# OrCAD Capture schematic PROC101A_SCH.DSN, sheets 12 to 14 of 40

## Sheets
12 34.MCU GENERAL&SAFETY CONNECTOR: size C; title: MCU GENERAL & SAFETY CONNECTOR
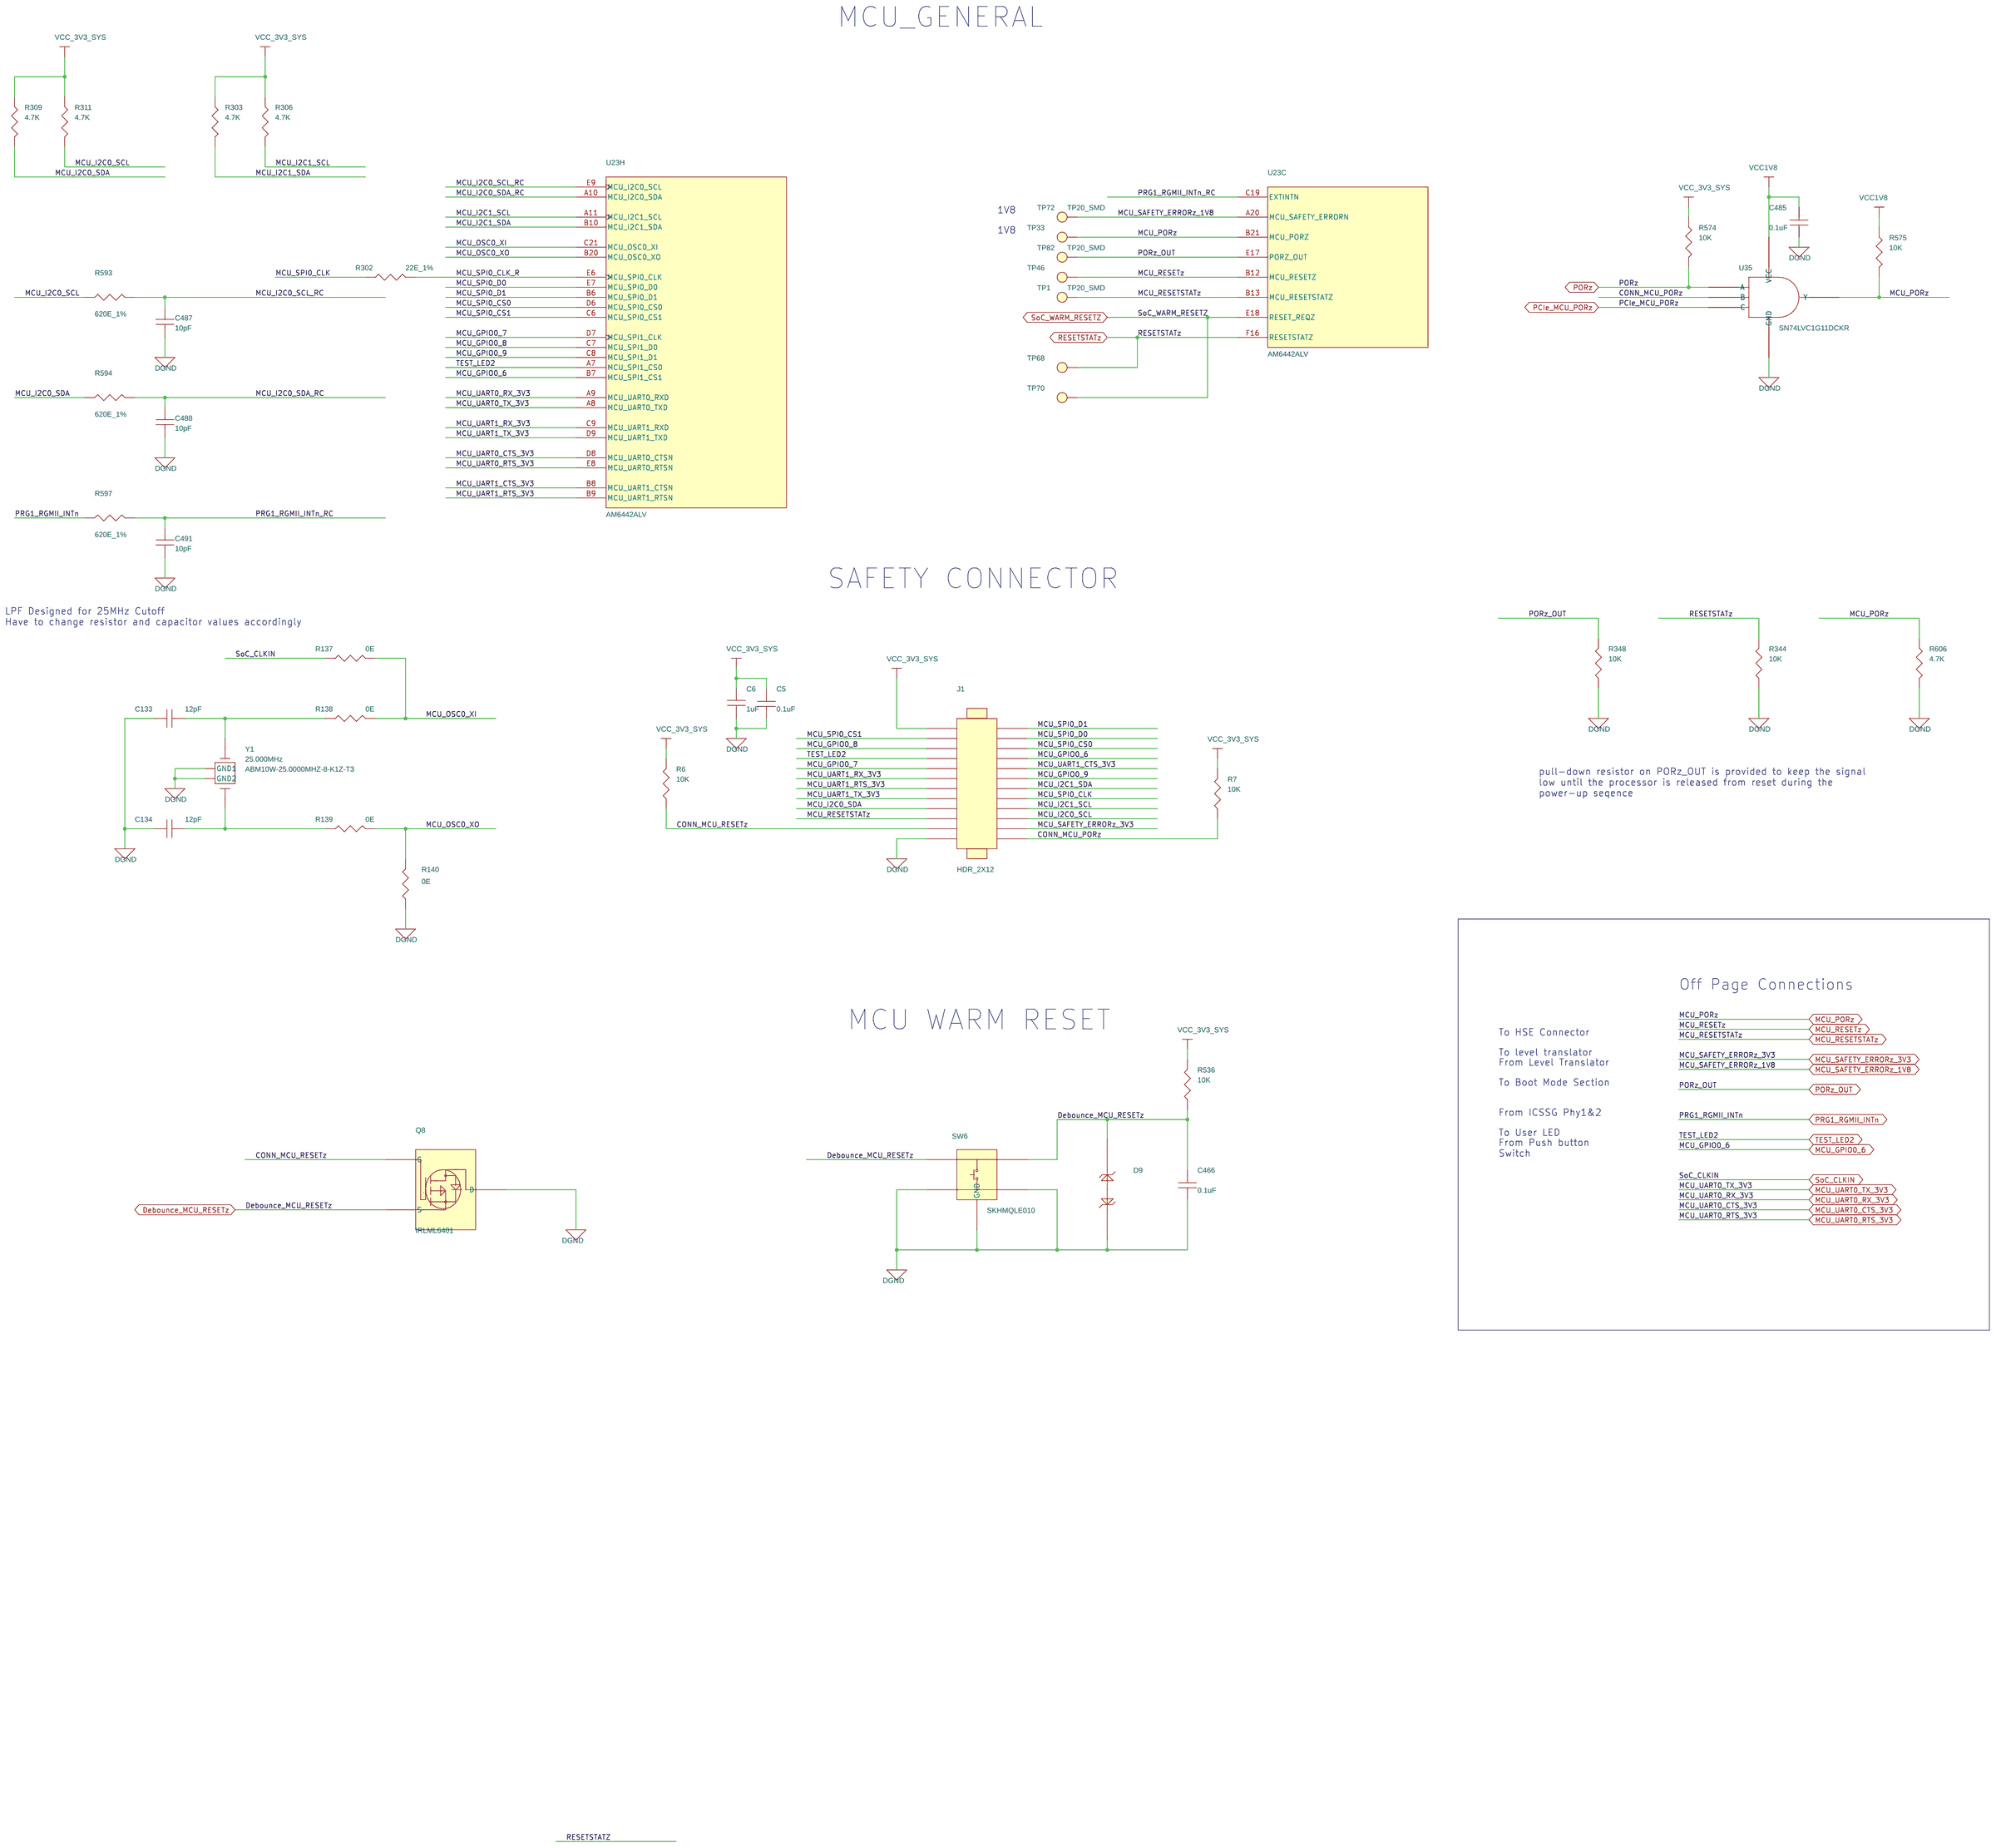
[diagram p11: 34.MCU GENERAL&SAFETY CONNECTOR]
13 33. IO EXPANDER & TEST HEADER: size C; title: IO EXPANDER
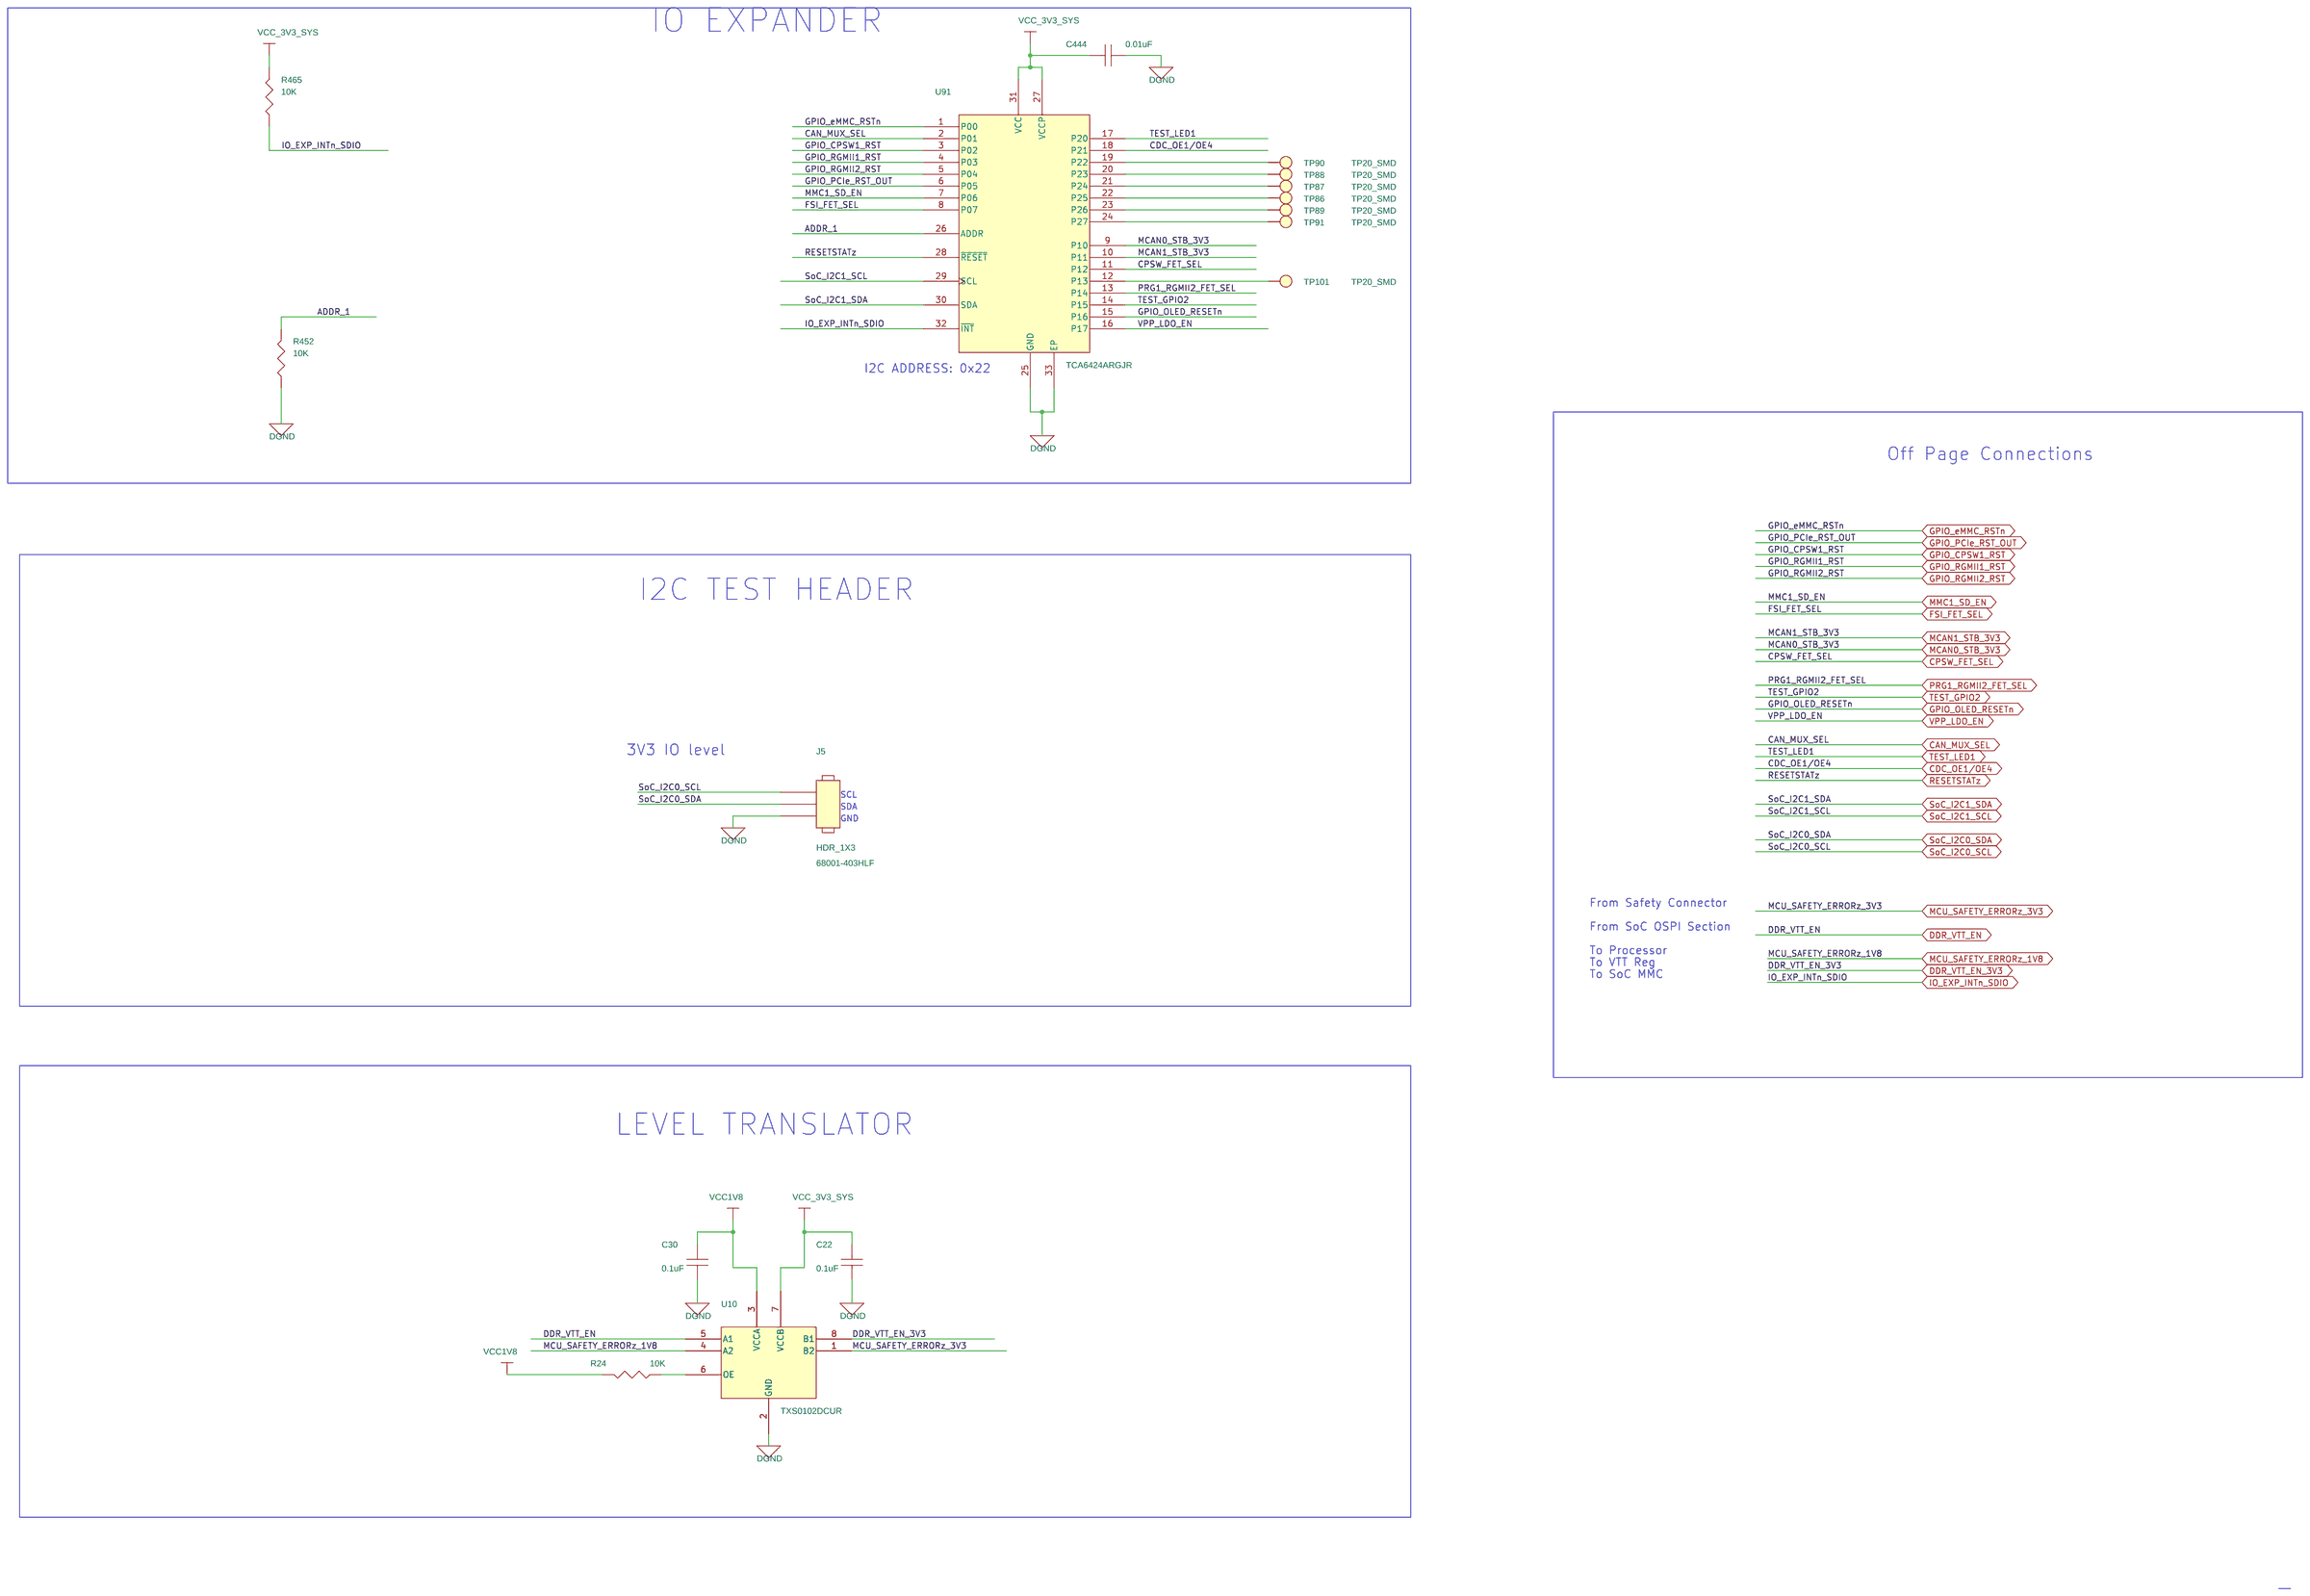
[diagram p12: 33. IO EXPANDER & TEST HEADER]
14 21. CURRENT MONITORING DEVICES: size C; title: CURRENT MONITORING DEVICES
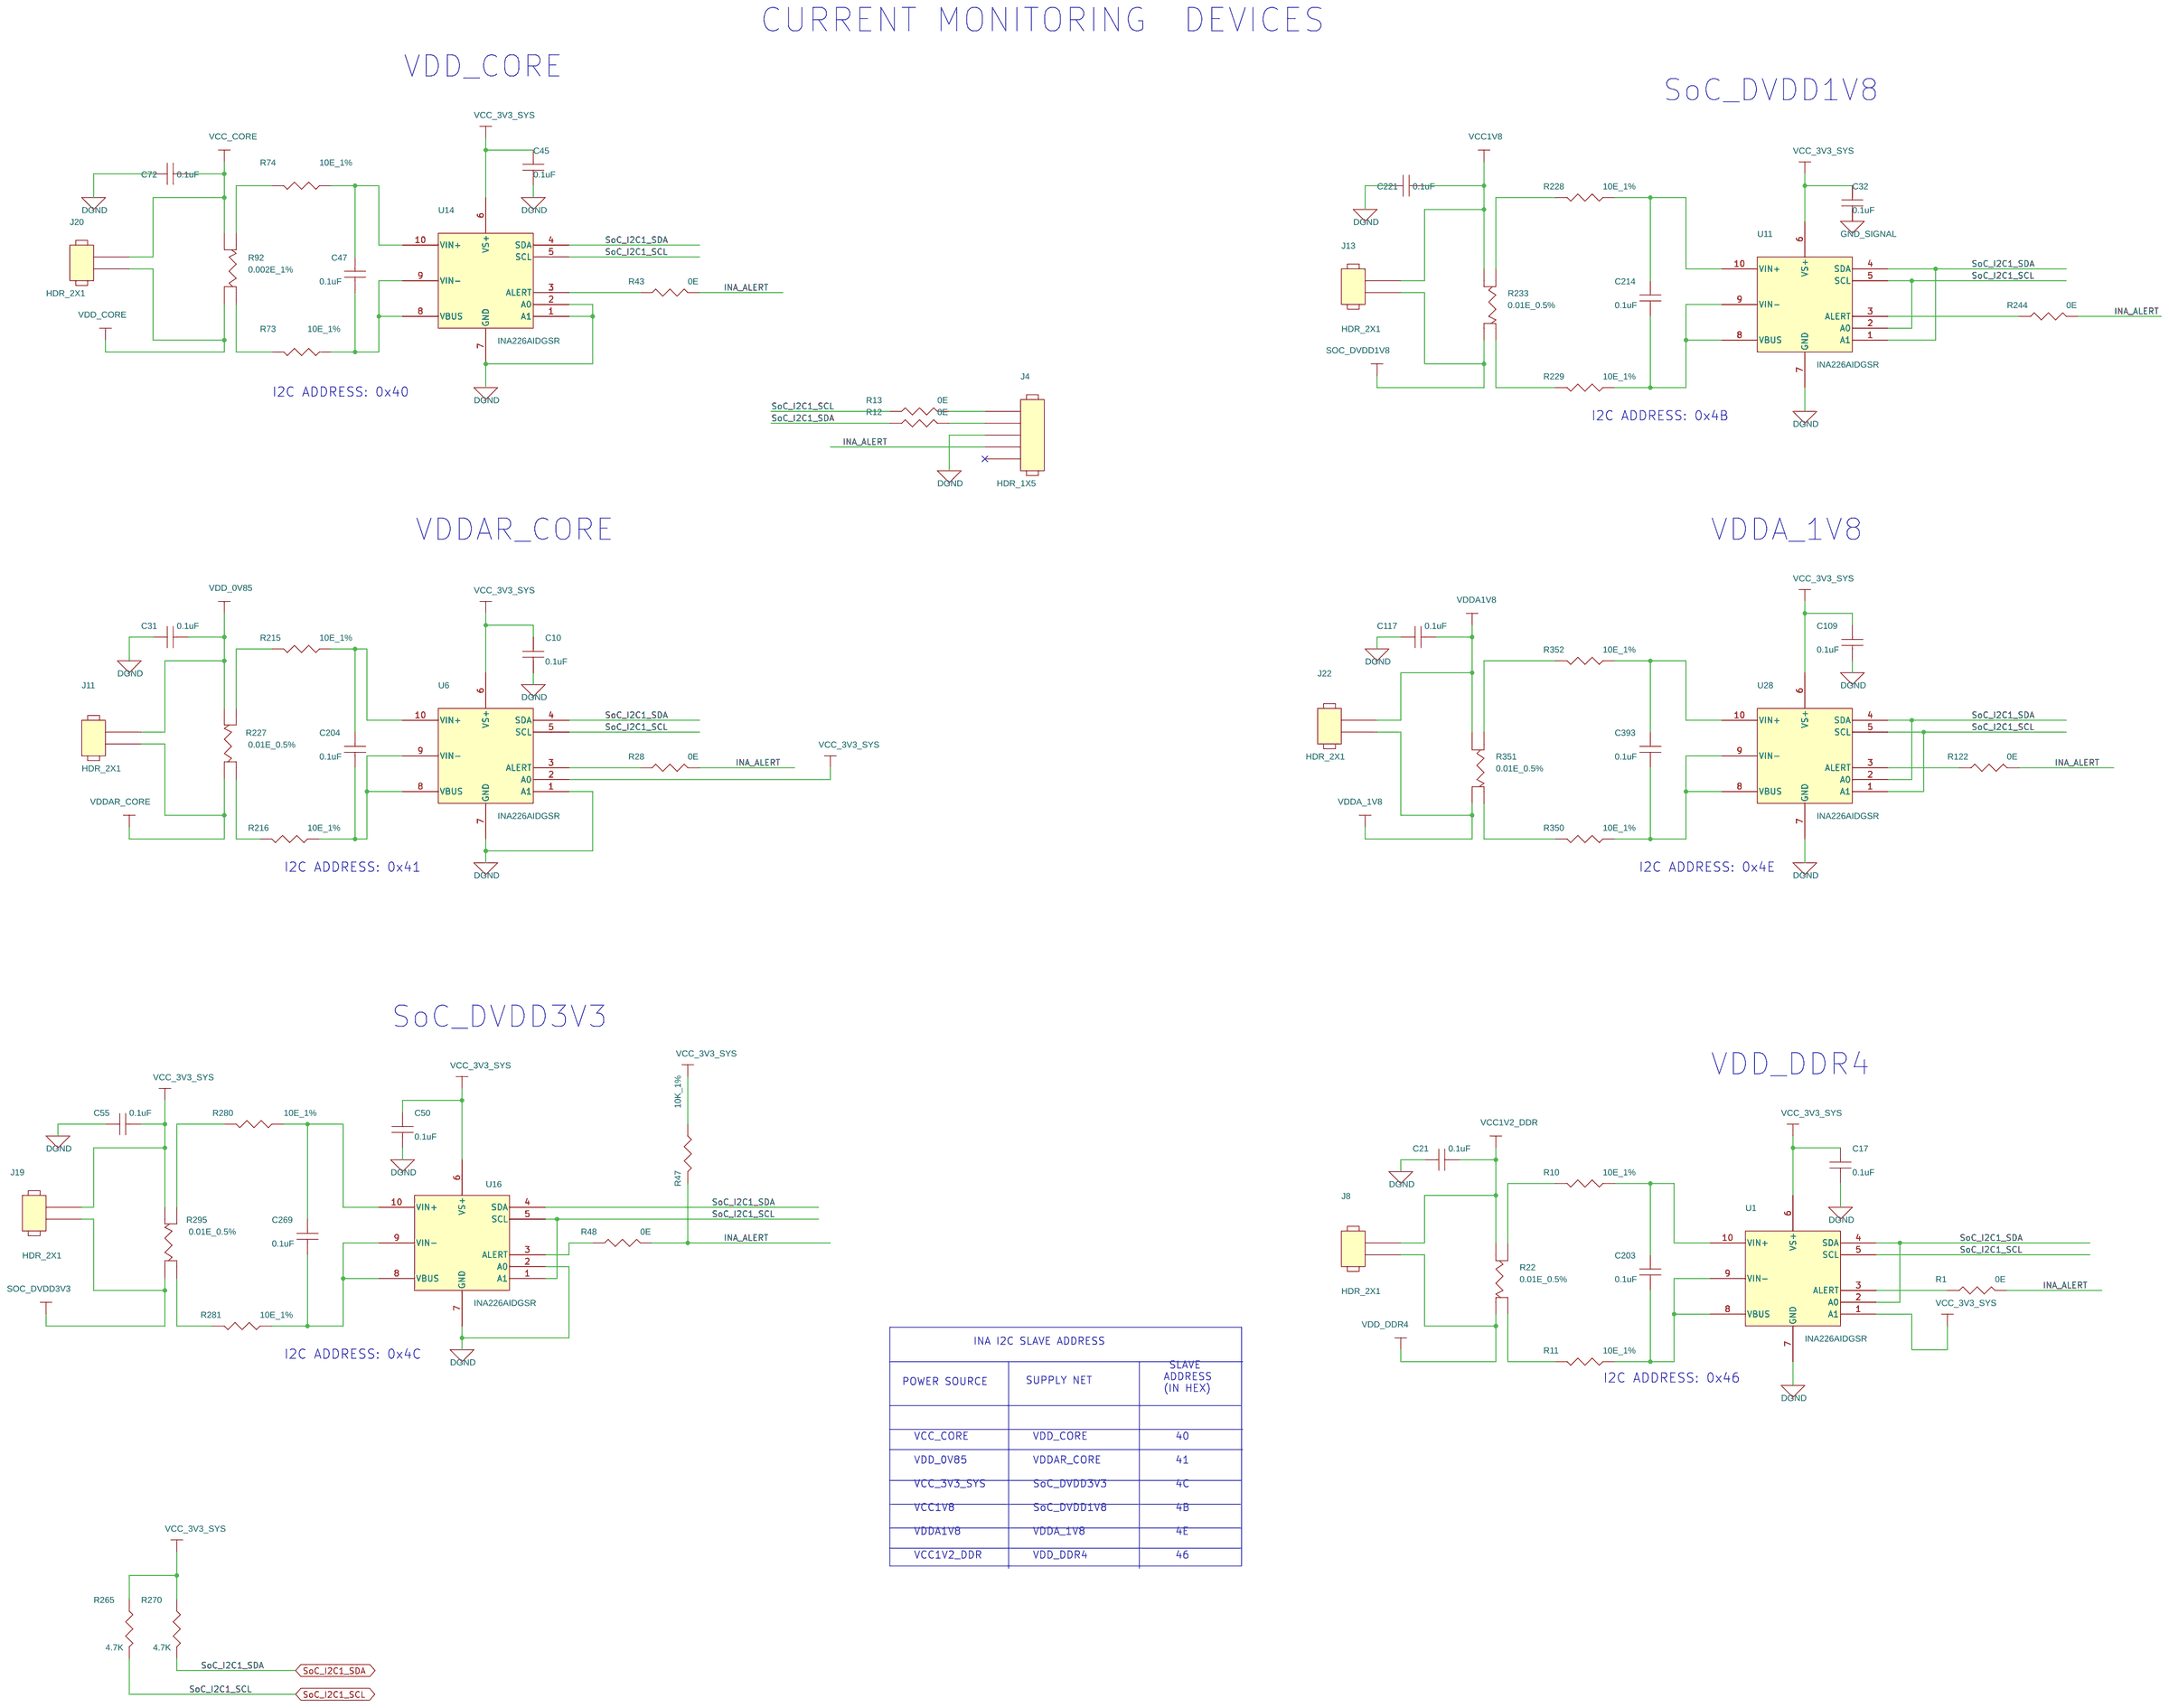
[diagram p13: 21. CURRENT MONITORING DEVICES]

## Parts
sheet 21. CURRENT MONITORING DEVICES
C10  0.1uF  [CAP0402_0-75]
C17  0.1uF  [CAP0402_0-75]
C21  0.1uF  [CAP0402_0-75]
C31  0.1uF  [CAP0402_0-75]
C32  0.1uF  [CAP0402_0-75]
C45  0.1uF  [CAP0402_0-75]
C47  0.1uF  [CAP0402_0-75]
C50  0.1uF  [CAP0402_0-75]
C55  0.1uF  [CAP0402_0-75]
C72  0.1uF  [CAP0402_0-75]
C109  0.1uF  [CAP0402_0-75]
C117  0.1uF  [CAP0402_0-75]
C203  0.1uF  [CAP0402_0-75]
C204  0.1uF  [CAP0402_0-75]
C214  0.1uF  [CAP0402_0-75]
C221  0.1uF  [CAP0402_0-75]
C269  0.1uF  [CAP0402_0-75]
C393  0.1uF  [CAP0402_0-75]
J4  HDR_1X5  [HDR_5X1_100_S_T_11-2]
J8  HDR_2X1  [HDR_2X1_100_S_T_10-8]
J11  HDR_2X1  [HDR_2X1_100_S_T_10-8]
J13  HDR_2X1  [HDR_2X1_100_S_T_10-8]
J19  HDR_2X1  [HDR_2X1_100_S_T_10-8]
J20  HDR_2X1  [HDR_2X1_100_S_T_10-8]
J22  HDR_2X1  [HDR_2X1_100_S_T_10-8]
R1  0E  [RES0402_0-5]
R10  10E_1%  [RES0402_0-5]
R11  10E_1%  [RES0402_0-5]
R12  0E  [RES0402_0-5]
R13  0E  [RES0402_0-5]
R22  0.01E_0.5%  [RES1206-4TERM_0-75]
R28  0E  [RES0402_0-5]
R43  0E  [RES0402_0-5]
R47  10K_1%  [RES0402_0-5]
R48  0E  [RES0402_0-5]
R73  10E_1%  [RES0402_0-5]
R74  10E_1%  [RES0402_0-5]
R92  0.002E_1%  [RES2512-4TERM_0-75]
R122  0E  [RES0402_0-5]
R215  10E_1%  [RES0402_0-5]
R216  10E_1%  [RES0402_0-5]
R227  0.01E_0.5%  [RES1206-4TERM_0-75]
R228  10E_1%  [RES0402_0-5]
R229  10E_1%  [RES0402_0-5]
R233  0.01E_0.5%  [RES1206-4TERM_0-75]
R244  0E  [RES0402_0-5]
R265  4.7K  [RES0402_0-5]
R270  4.7K  [RES0402_0-5]
R280  10E_1%  [RES0402_0-5]
R281  10E_1%  [RES0402_0-5]
R295  0.01E_0.5%  [RES1206-4TERM_0-75]
R350  10E_1%  [RES0402_0-5]
R351  0.01E_0.5%  [RES1206-4TERM_0-75]
R352  10E_1%  [RES0402_0-5]
U1  INA226AIDGSR  [MSOP10_19-68_120X120_1-1]
U6  INA226AIDGSR  [MSOP10_19-68_120X120_1-1]
U11  INA226AIDGSR  [MSOP10_19-68_120X120_1-1]
U14  INA226AIDGSR  [MSOP10_19-68_120X120_1-1]
U16  INA226AIDGSR  [MSOP10_19-68_120X120_1-1]
U28  INA226AIDGSR  [MSOP10_19-68_120X120_1-1]
sheet 28.GPMC & FSI CONNECTOR
U23  AM6442ALV  [FCBGA441_31-49_680X680_2-6]  (sections A,B,C,D,E,F,G,H,I,J,K,L,M,N,O,P)
sheet 33. IO EXPANDER & TEST HEADER
C22  0.1uF  [CAP0402_0-75]
C30  0.1uF  [CAP0402_0-75]
C444  0.01uF  [CAP0402_0-75]
J5  HDR_1X3  [HDR_3X1_100_S_T]
R24  10K  [RES0402_0-5]
R452  10K  [RES0402_0-5]
R465  10K  [RES0402_0-5]
TP86  TP20_SMD  [TP20_SMD]
TP87  TP20_SMD  [TP20_SMD]
TP88  TP20_SMD  [TP20_SMD]
TP89  TP20_SMD  [TP20_SMD]
TP90  TP20_SMD  [TP20_SMD]
TP91  TP20_SMD  [TP20_SMD]
TP101  TP20_SMD  [TP20_SMD]
U10  TXS0102DCUR  [VSSOP8_19-68_85X95_0-9]
U91  TCA6424ARGJR  [QFN32_19-68_200X200]
sheet 34.MCU GENERAL&SAFETY CONNECTOR
C5  0.1uF  [CAP0402_0-75]
C6  1uF  [CAP0402_0-75]
C133  12pF  [CAP0201_0-5]
C134  12pF  [CAP0201_0-5]
C466  0.1uF  [CAP0402_0-75]
C485  0.1uF  [CAP0402_0-75]
C487  10pF  [CAP0402_0-75]
C488  10pF  [CAP0402_0-75]
C491  10pF  [CAP0402_0-75]
D9  TPD1E10B06DPYR  [DIO_DFN0402_0-5]
J1  HDR_2X12  [HDR_2X12_TSW-112-07-D_S_T_8-6]
Q8  IRLML6401  [TO_SOT23-123]
R6  10K  [RES0402_0-5]
R7  10K  [RES0402_0-5]
R137  0E  [RES0402_0-5]
R138  0E  [RES0402_0-5]
R139  0E  [RES0402_0-5]
R140  0E  [RES0402_0-5]
R302  22E_1%  [RES0402_0-5]
R303  4.7K  [RES0402_0-5]
R306  4.7K  [RES0402_0-5]
R309  4.7K  [RES0402_0-5]
R311  4.7K  [RES0402_0-5]
R344  10K  [RES0402_0-5]
R348  10K  [RES0402_0-5]
R536  10K  [RES0402_0-5]
R574  10K  [RES0402_0-5]
R575  10K  [RES0402_0-5]
R593  620E_1%  [RES0402_0-5]
R594  620E_1%  [RES0402_0-5]
R597  620E_1%  [RES0402_0-5]
R606  4.7K  [RES0402_0-5]
SW6  SKHMQLE010  [SW4_SKHMQLE010_240X260_SMD_3-1]
TP1  TP20_SMD  [TP20_SMD]
TP33  TP20_SMD  [TP20_SMD]
TP46  TP20_SMD  [TP20_SMD]
TP68  TP20_SMD  [TP20_SMD]
TP70  TP20_SMD  [TP20_SMD]
TP72  TP20_SMD  [TP20_SMD]
TP82  TP20_SMD  [TP20_SMD]
U35  SN74LVC1G11DCKR  [SC70-6]
Y1  25.000MHz  [XTAL4_ABM10W_100X80_SMD_0-6]

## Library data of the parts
C5 C10 C17 C21 C22 C30-C32 C45 C47 C50 C55 C72 C109 C117 C203 C204 C214 C221 C269 C393 C466 C485 = CAP: CAP CERAMIC 0.1uF 25V 20% X5R 0402; Alt_Mfr_name: YAGEO AMERICA; Alt_Mfr_part_number: CC0402KRX5R8BB104; Chkd/date: MANIRAJA/170820; Crtd /date: ALVY/170820; Custom_Duty: 15%; Customs_HS_Code: 85322990; Distributor_name: DIGIKEY; Distributor_part_number: 732-7495-1-ND; Footprint Path: Y:\MIS_DATABASE\Library\ALTIUM_TOOL\PCB_FOOTPRINTS\Altium_Footprint_Lib.PcbLib; Height: 0.55MM; Library Path: Y:\MIS_DATABASE\Library\ALTIUM_TOOL\SCHEMATICS_PARTS\MS_DISCRETE_Library.schlib; Mfr_name: WURTH ELECTRONICS; Mfr_part_number: 885012105018; Mistral Part No: 120020080003-R; Package: 0402; Part_type: CAPACITORS\CERAMIC; Project: AM64x_EVM_BRD; RoHS: RoHS; Temperature: -55°C+85°C; Tolerance: 20%; Voltage: 25V; Wattage: NA; Weight: 0.65mg; Datasheet: Y:\MIS_DATABASE\DATASHEETS\CAPACITORS\885012105018.PDF
J4 = HEADER_5X1: CON HDR 1X5 2.54MM PITCH ST TH; Chkd/date: VASANTHA/310117; Crtd /date: MAZHAR/280405; Custom_Duty: 24%; Customs_HS_Code: 85369090; Distributor_name: DIGIKEY; Distributor_part_number: WM4003-ND; Footprint Path: Y:\MIS_DATABASE\Library\ALTIUM_TOOL\PCB_FOOTPRINTS\Altium_Footprint_Lib.PcbLib; Height: 11.17MM; Library Path: Y:\MIS_DATABASE\Library\ALTIUM_TOOL\SCHEMATICS_PARTS\MS_CONNECTOR_Library.schlib; Mfr_name: MOLEX; Mfr_part_number: 22-03-2051; Mistral Part No: 150009030262-R; Package: THRU-HOLE; Part_type: CONNECTOR\HEADERS; Project: HSWD; RoHS: RoHS; Temperature: NA; Tolerance: NA; Voltage: NA; Wattage: NA; Weight: 343mg; Datasheet: Y:\MIS_DATABASE\DATASHEETS\CONNECTORS\MOLEX022032021.PDF
J8 J11 J13 J19 J20 J22 = HEADER_2X1: CON HDR 2X1 2.54MM PITCH ST TH; Chkd/date: VASANTHA/060117; Crtd /date: MAZHAR/280405; Custom_Duty: 24%; Customs_HS_Code: 85369090; Distributor_name: DIGIKEY; Distributor_part_number: WM4000-ND; Footprint Path: Y:\MIS_DATABASE\Library\ALTIUM_TOOL\PCB_FOOTPRINTS\Altium_Footprint_Lib.PcbLib; Height: 10.79MM; Library Path: Y:\MIS_DATABASE\Library\ALTIUM_TOOL\SCHEMATICS_PARTS\MS_Connector_Library.schlib; Mfr_name: MOLEX; Mfr_part_number: 22-03-2021; Mistral Part No: 150009030246-R; Package: THRU-HOLE; Part_type: CONNECTOR\HEADERS; Project: FPGA EXTENDER CARD; RoHS: RoHS; Temperature: -0°C+75°C; Tolerance: NA; Voltage: NA; Wattage: NA; Weight: 139gm; Datasheet: Y:\MIS_DATABASE\DATASHEETS\CONNECTORS\HEADER_X4030.PDF
R1 R12 R13 R28 R43 R48 R122 R137-R140 R244 = RESISTOR: RES 0E 1/16W JUMPER 0402; Chkd/date: VASANTHA/201216; Crtd /date: MUDDU/190810; Custom_Duty: 15%; Customs_HS_Code: 85332119; Distributor_name: DIGIKEY; Distributor_part_number: 541-0.0JCT-ND; Footprint Path: Y:\MIS_DATABASE\Library\ALTIUM_TOOL\PCB_FOOTPRINTS\Altium_Footprint_Lib.PcbLib; Height: 0.40MM; Library Path: Y:\MIS_DATABASE\Library\ALTIUM_TOOL\SCHEMATICS_PARTS\MS_DISCRETE_Library.schlib; Mfr_name: VISHAY; Mfr_part_number: CRCW04020000Z0ED; Mistral Part No: 110010080019-R; Package: 0402; Part_type: RESISTORS\FIXED; Project: PB_BUGBASE; RoHS: RoHS; Temperature: -55°C+155°C; Tolerance: NA; Voltage: NA; Wattage: 1/16W; Weight: 0.65mg; Datasheet: Y:\MIS_DATABASE\DATASHEETS\RESISTORS\CRCW0603.PDF
R10 R11 R73 R74 R215 R216 R228 R229 R280 R281 R350 R352 = RESISTOR: RES 10E 1/16W 1% 0402; Chkd/date: MANIRAJA/070218; Crtd /date: ALVY/070218; Custom_Duty: 15%; Customs_HS_Code: 85332119; Distributor_name: DIGIKEY; Distributor_part_number: 311-10.0LRCT-ND; Footprint Path: Y:\MIS_DATABASE\Library\ALTIUM_TOOL\PCB_FOOTPRINTS\Altium_Footprint_Lib.PcbLib; Height: 0.40MM; Library Path: Y:\MIS_DATABASE\Library\ALTIUM_TOOL\SCHEMATICS_PARTS\MS_DISCRETE_Library.schlib; Mfr_name: YAGEO AMERICA; Mfr_part_number: RC0402FR-0710RL; Mistral Part No: 110018020004-R; Package: 0402; Part_type: RESISTORS\FIXED; Project: TI_MAXIE_CPB; RoHS: RoHS; Temperature: -55°C+155°C; Tolerance: 1%; Voltage: NA; Wattage: 1/16W; Weight: 0.65mg; Datasheet: Y:\MIS_DATABASE\DATASHEETS\RESISTORS\RCXXXXL-SER_MAR18.PDF
R22 R227 R233 R295 R351 = RESISTOR-4TERM: RES 0.01E 1/2W 0.5% 1206-4; Chkd/date: MANIRAJA/260917; Crtd /date: MANIRAJA/260917; Custom_Duty: 15%; Customs_HS_Code: 85332119; Distributor_name: DIGIKEY; Distributor_part_number: LVK12R010DERCT-ND; Footprint Path: Y:\MIS_DATABASE\Library\ALTIUM_TOOL\PCB_FOOTPRINTS\Altium_Footprint_Lib.PcbLib; Height: 0.65MM; Library Path: Y:\MIS_DATABASE\Library\ALTIUM_TOOL\SCHEMATICS_PARTS\MS_DISCRETE_Library.schlib; Mfr_name: OHMITE; Mfr_part_number: LVK12R010DER; Mistral Part No: 110017090009-R; Package: 1206-4; Part_type: RESISTORS\FIXED; Project: TI_MAXIE_CPB; RoHS: RoHS; Temperature: -40°C+125°C; Tolerance: 0.5%; Voltage: NA; Wattage: 1/2W; Weight: 16.2mg; Datasheet: Y:\MIS_DATABASE\DATASHEETS\RESISTORS\LVK-SERIES.PDF
R47 = RESISTOR: RES 10K 1/16W 1% 0402; Chkd/date: VASANTHA/201216; Crtd /date: GEETHA/290506; Custom_Duty: 15%; Customs_HS_Code: 85332119; Distributor_name: DIGIKEY; Distributor_part_number: 311-10.0KLRTR-ND; Footprint Path: Y:\MIS_DATABASE\Library\ALTIUM_TOOL\PCB_FOOTPRINTS\Altium_Footprint_Lib.PcbLib; Height: 0.40MM; Library Path: Y:\MIS_DATABASE\Library\ALTIUM_TOOL\SCHEMATICS_PARTS\MS_DISCRETE_Library.schlib; Mfr_name: YAGEO AMERICA; Mfr_part_number: RC0402FR-0710KL; Mistral Part No: 110015090015-R; Package: 0402; Part_type: RESISTORS\FIXED; Project: VOCERA; RoHS: RoHS; Temperature: -55°C+155°C; Tolerance: 1%; Voltage: NA; Wattage: 1/16W; Weight: 0.65mg; Datasheet: Y:\MIS_DATABASE\DATASHEETS\RESISTORS\RCXXXXL-SER_MAR18.PDF
R92 = RESISTOR-4TERM: RES 0.002E 2W 1% 2512-4; Chkd/date: MANIRAJA/260917; Crtd /date: MANIRAJA/260917; Custom_Duty: 15%; Customs_HS_Code: 85332119; Distributor_name: DIGIKEY; Distributor_part_number: LVK25R002FERCT-ND; Footprint Path: Y:\MIS_DATABASE\Library\ALTIUM_TOOL\PCB_FOOTPRINTS\Altium_Footprint_Lib.PcbLib; Height: 0.70MM; Library Path: Y:\MIS_DATABASE\Library\ALTIUM_TOOL\SCHEMATICS_PARTS\MS_DISCRETE_Library.schlib; Mfr_name: OHMITE; Mfr_part_number: LVK25R002FER; Mistral Part No: 110017090010-R; Package: 2512-4; Part_type: RESISTORS\FIXED; Project: TI_MAXIE_CPB; RoHS: RoHS; Temperature: -40°C+125°C; Tolerance: 1%; Voltage: NA; Wattage: 2W; Weight: NA; Datasheet: Y:\MIS_DATABASE\DATASHEETS\RESISTORS\LVK-SERIES.PDF
R265 R270 R303 R306 R309 R311 R606 = RESISTOR: RES 4.7K 1/16W 5% 0402; Chkd/date: VASANTHA/130516; Crtd /date: VASANTHA/130516; Custom_Duty: 15%; Customs_HS_Code: 85332119; Distributor_name: DIGIKEY; Distributor_part_number: 311-4.7KJRCT-ND; Footprint Path: Y:\MIS_DATABASE\Library\ALTIUM_TOOL\PCB_FOOTPRINTS\Altium_Footprint_Lib.PcbLib; Height: 0.40MM; Library Path: Y:\MIS_DATABASE\Library\ALTIUM_TOOL\SCHEMATICS_PARTS\MS_DISCRETE_Library.schlib; Mfr_name: YAGEO AMERICA; Mfr_part_number: RC0402JR-074K7L; Mistral Part No: 110011060001-R; Package: 0402; Part_type: RESISTORS\FIXED; Project: TMDXCSK368; RoHS: RoHS; Temperature: -55°C+155°C; Tolerance: 5%; Voltage: NA; Wattage: 1/16W; Weight: 0.65mg; Datasheet: Y:\MIS_DATABASE\DATASHEETS\RESISTORS\RCXXXXL-SER_MAR18.PDF
U1 U6 U11 U14 U16 U28 = INA226AIDGS_MSOP10: IC BI-DIRECTIONAL CURRENT MONITER MSOP10; Chkd/date: MANIRAJA/050417; Crtd /date: MANIRAJA/050417; Custom_Duty: 15%; Customs_HS_Code: 85423100; Distributor_name: DIGIKEY; Distributor_part_number: 296-29034-1-ND; Footprint Path: Y:\MIS_DATABASE\Library\ALTIUM_TOOL\PCB_FOOTPRINTS\Altium_Footprint_Lib.PcbLib; Height: 1.10MM; Library Path: Y:\MIS_DATABASE\Library\ALTIUM_TOOL\SCHEMATICS_PARTS\MS_MISCINTERFACE_Library.schlib; Mfr_name: TEXAS INSTRUMENTS; Mistral Part No: 141011080019-R; Package: MSOP10; Part_type: ICS\INTERFACE; Project: DM385EVM_BASE-BOARD; RoHS: RoHS; Temperature: -40°C+125°C; Tolerance: NA; Voltage: NA; Wattage: NA; Weight: NA; Datasheet: Y:\MIS_DATABASE\DATASHEETS\ICS\INTERFACE\INA226.PDF
U23 = AM64-SVB_BGA441: IC AM64 SoC MICROPROCESSOR BGA441; Chkd/date: MANIRAJA/020520; Crtd /date: ALVY/090420; Custom_Duty: 15%; Customs_HS_Code: 85423100; Distributor_name: NA; Distributor_part_number: NA; Footprint Path: Y:\MIS_DATABASE\Library\ALTIUM_TOOL\PCB_FOOTPRINTS\Altium_Footprint_Lib.PcbLib; Height: 2.57MM; Library Path: Y:\MIS_DATABASE\Library\ALTIUM_TOOL\SCHEMATICS_PARTS\MS_MICROPROCESSOR_Library.schlib; Mfr_name: TEXAS INSTRUMENTS; Mfr_part_number: AM6442ASFGGAALV; Mistral Part No: 141220040002; Package: BGA441; Part_type: ICS\DIGITAL\MICROPROCESSOR; Project: AM64x_SVB BRD; RoHS: NA; Temperature: NA; Tolerance: NA; Voltage: NA; Wattage: NA; Weight: NA; Datasheet: Y:\MIS_DATABASE\DATASHEETS\ICS\DIGITAL\MICROCONTROLLER\AM64-SoC_SVB.PDF
C444 = CAP: CAP CERAMIC 0.01uF 25V 10% X7R 0402; Chkd/date: MANIRAJA/170820; Crtd /date: ALVY/170820; Custom_Duty: 15%; Customs_HS_Code: 85322990; Distributor_name: DIGIKEY; Distributor_part_number: 732-7545-1-ND; Footprint Path: Y:\MIS_DATABASE\Library\ALTIUM_TOOL\PCB_FOOTPRINTS\Altium_Footprint_Lib.PcbLib; Height: 0.55MM; Library Path: Y:\MIS_DATABASE\Library\ALTIUM_TOOL\SCHEMATICS_PARTS\MS_DISCRETE_Library.schlib; Mfr_name: WURTH ELECTRONICS; Mfr_part_number: 885012205050; Mistral Part No: 120011090040-R; Package: 0402; Part_type: CAPACITORS\CERAMIC; Project: AM64x_EVM_BRD; RoHS: RoHS; Temperature: -55°C+125°C; Tolerance: 10%; Voltage: 25V; Wattage: NA; Weight: 0.65mg; Datasheet: Y:\MIS_DATABASE\DATASHEETS\CAPACITORS\885012205050.PDF
J5 = HEADER_3X1: HDR 1X3 2.54MM PITCH ST TH; Chkd/date: VASANTHA/290616; Crtd /date: VASANTHA/290616; Custom_Duty: 15%; Customs_HS_Code: 85322990; Distributor_name: DIGIKEY; Distributor_part_number: 609-3471-ND; Height: 8.58MM; Mfr_name: FCI; Mfr_part_number: 68001-403HLF; Mistral Part No: 150016060025-R; Package: THRU-HOLE; Part_type: CONNECTOR\HEADERS; Project: IKEYP; RoHS: RoHS; Temperature: -40°C+105°C; Tolerance: NA; Voltage: NA; Wattage: NA; Weight: NA; Datasheet: Y:\MIS_DATABASE\DATASHEETS\CONNECTORS\68000.PDF
R6 R7 R24 R344 R348 R452 R465 R536 R574 R575 = RESISTOR: RES 10K 1/16W 5% 0402; Chkd/date: VASANTHA/061216; Crtd /date: MAZHAR/230805; Custom_Duty: 15%; Customs_HS_Code: 85332119; Distributor_name: DIGIKEY; Distributor_part_number: 311-10KJRCT-ND; Footprint Path: Y:\MIS_DATABASE\Library\ALTIUM_TOOL\PCB_FOOTPRINTS\Altium_Footprint_Lib.PcbLib; Height: 0.40MM; Library Path: Y:\MIS_DATABASE\Library\ALTIUM_TOOL\SCHEMATICS_PARTS\MS_DISCRETE_Library.schlib; Mfr_name: YAGEO AMERICA; Mfr_part_number: RC0402JR-0710KL; Mistral Part No: 110011060021-R; Package: 0402; Part_type: RESISTORS\FIXED; Project: HSE; RoHS: RoHS; Temperature: -55°C+155°C; Tolerance: 5%; Voltage: NA; Wattage: 1/16W; Weight: 0.65mg; Datasheet: Y:\MIS_DATABASE\DATASHEETS\RESISTORS\RCXXXXL-SER_MAR18.PDF
TP1 TP33 TP46 TP68 TP70 TP72 TP82 TP86-TP91 TP101 = TESTPOINT: TESTPOINT CIR 20 SMD; Chkd/date: SHREESHAIL/171006; Crtd /date: MAZHAR/171006; Custom_Duty: NA; Customs_HS_Code: NA; Distributor_name: NA; Distributor_part_number: NA; Footprint Path: Y:\MIS_DATABASE\Library\ALTIUM_TOOL\PCB_FOOTPRINTS\Altium_Footprint_Lib.PcbLib; Height: NA; Library Path: Y:\MIS_DATABASE\Library\ALTIUM_TOOL\SCHEMATICS_PARTS\MS_DISCRETE_Library.schlib; MECHANICAL 3D STEP FILE: NA; Mfr_name: LOCAL; Mistral Part No: NA; Package: SMD; Project: BT MODULE_CSRBC04; RoHS: NA; Temperature: NA; Tolerance: NA; Voltage: NA; Wattage: NA; Weight: NA; Datasheet: NA
U10 = TXS0102DCUR_VSSOP8: IC 2BIT BI-DIR VOLTAGE-LEVEL TRANSLATOR US8(VSSOP8); Chkd/date: MANIRAJA/130617; Crtd /date: SHREESHAIL/190108; Custom_Duty: 15%; Customs_HS_Code: 85423100; Distributor_name: DIGIKEY; Distributor_part_number: 296-21931-1-ND; Footprint Path: Y:\MIS_DATABASE\Library\ALTIUM_TOOL\PCB_FOOTPRINTS\Altium_Footprint_Lib.PcbLib; Height: 0.90MM; Library Path: Y:\MIS_DATABASE\Library\ALTIUM_TOOL\SCHEMATICS_PARTS\MS_MISCINTERFACE_Library.schlib; Mfr_name: TEXAS INSTRUMENTS; Mistral Part No: 141009030376-R; Package: US8; Part_type: ICS\INTERFACE\LEVEL TRANSLATOR; Project: SD_WATERLOO; RoHS: RoHS; Temperature: -40°C+85°C; Tolerance: NA; Voltage: NA; Wattage: NA; Weight: 9.6mg; Datasheet: Y:\MIS_DATABASE\DATASHEETS\ICS\INTERFACE\TXS0102.PDF
U91 = TCA6424ARGJR_QFN32: IC I2C I/O EXPANDER 24B UQFN32; Chkd/date: NAVEED/100715; Crtd /date: NAVEED/100914; Custom_Duty: 15%; Customs_HS_Code: 85423100; Distributor_name: DIGIKEY; Distributor_part_number: 296-27844-1-ND; Height: 0.60MM; Mfr_name: TEXAS INSTRUMENTS; Mistral Part No: 141014090009-R; Package: UQFN32; Part_type: ICS\DIGITAL\BUSTRANSCEIVER; Project: ZK_BIOMETRIC; RoHS: RoHS; Temperature: -40°C+85°C; Weight: NA; Datasheet: Y:\MIS_DATABASE\DATASHEETS\ICS\DIGITAL\BUSTRANSCEIVER\TCA6424AR.PDF
C6 = CAP: CAP CERAMIC 1uF 10V 20% X5R 0402; Chkd/date: MANIRAJA/210820; Crtd /date: ALVY/190820; Custom_Duty: 15%; Customs_HS_Code: 85322990; Distributor_name: DIGIKEY; Distributor_part_number: 732-7489-1-ND; Footprint Path: Y:\MIS_DATABASE\Library\ALTIUM_TOOL\PCB_FOOTPRINTS\Altium_Footprint_Lib.PcbLib; Height: 0.55MM; Library Path: Y:\MIS_DATABASE\Library\ALTIUM_TOOL\SCHEMATICS_PARTS\MS_DISCRETE_Library.schlib; Mfr_name: WURTH ELECTRONICS; Mfr_part_number: 885012105012; Mistral Part No: 120020080009-R; Package: 0402; Part_type: CAPACITORS\CERAMIC; Project: AM64x_EVM_BRD; RoHS: RoHS; Temperature: -55°C+85°C; Tolerance: 20%; Voltage: 10V; Wattage: NA; Weight: 0.65mg; Datasheet: Y:\MIS_DATABASE\DATASHEETS\CAPACITORS\885012105012.PDF
C133 C134 = CAP: CAP CERAMIC 12pF 25V 5% C0G(NP0) 0201; Chkd/date: MANIRAJA/020620; Crtd /date: ALVY/300520; Custom_Duty: 15%; Customs_HS_Code: 85322990; Distributor_name: DIGIKEY; Distributor_part_number: 490-3144-1-ND; Footprint Path: Y:\MIS_DATABASE\Library\ALTIUM_TOOL\PCB_FOOTPRINTS\Altium_Footprint_Lib.PcbLib; Height: 0.33MM; Library Path: Y:\MIS_DATABASE\Library\ALTIUM_TOOL\SCHEMATICS_PARTS\MS_DISCRETE_Library.schlib; Mfr_name: MURATA; Mfr_part_number: GRM0335C1E120JA01D; Mistral Part No: 120009030213-R; Package: 0201; Part_type: CAPACITORS\CERAMIC; Project: QCS610_NANOSOM; RoHS: RoHS; Temperature: -55°C+125°C; Tolerance: 5%; Voltage: 25V; Wattage: NA; Weight: 0.33mg; Datasheet: Y:\MIS_DATABASE\DATASHEETS\CAPACITORS\GRM0335C1E120JA01.PDF
C487 C488 C491 = CAP: CAP CERAMIC 10pF 16V 5% C0G(NP0) 0402; Chkd/date: MANIRAJA/100918; Crtd /date: ALVY/100918; Custom_Duty: 15%; Customs_HS_Code: 85322990; Distributor_name: DIGIKEY; Distributor_part_number: 732-7441-1-ND; Footprint Path: Y:\MIS_DATABASE\Library\ALTIUM_TOOL\PCB_FOOTPRINTS\Altium_Footprint_Lib.PcbLib; Height: 0.55MM; Library Path: Y:\MIS_DATABASE\Library\ALTIUM_TOOL\SCHEMATICS_PARTS\MS_DISCRETE_Library.schlib; Mfr_name: WURTH ELECTRONICS; Mfr_part_number: 885012005025; Mistral Part No: 120018030015-R; Package: 0402; Part_type: CAPACITORS\CERAMIC; Project: SMART-M_SCRIPTALK_PB; RoHS: RoHS; Temperature: -55°C+125°C; Tolerance: 5%; Voltage: 16V; Wattage: NA; Weight: 0.65mg; Datasheet: Y:\MIS_DATABASE\DATASHEETS\CAPACITORS\885012005025.PDF
D9 = DIODE_SOD323: DIODE 1CH ESD PROTECTION X1SON2; Chkd/date: MANIRAJA/040420; Crtd /date: VASANTHA/181114; Custom_Duty: 15%; Customs_HS_Code: 85423100; Distributor_name: DIGIKEY; Distributor_part_number: 296-30406-1-ND; Footprint Path: Y:\MIS_DATABASE\Library\ALTIUM_TOOL\PCB_FOOTPRINTS\Altium_Footprint_Lib.PcbLib; Height: 0.45MM; Library Path: Y:\MIS_DATABASE\Library\ALTIUM_TOOL\SCHEMATICS_PARTS\MS_DISCRETE_Library.schlib; Mfr_name: TEXAS INSTRUMENTS; Mistral Part No: 130014110022-R; Package: X1SON2; Part_type: DIODE; Project: GALILEO_EVM; RoHS: RoHS; Temperature: -40°C+125°C; Tolerance: NA; Voltage: NA; Wattage: NA; Weight: 1mg; Datasheet: Y:\MIS_DATABASE\DATASHEETS\ICS\INTERFACE\TPD1E10B06-SER.PDF
J1 = HEADER_12X2: CON HDR 2X12 2.54MM PITCH ST TH; Chkd/date: MANIRAJA/250420; Crtd /date: ALVY/240420; Custom_Duty: 24%; Customs_HS_Code: 85369090; Distributor_name: DIGIKEY; Distributor_part_number: SAM1032-12-ND; Footprint Path: Y:\MIS_DATABASE\Library\ALTIUM_TOOL\PCB_FOOTPRINTS\Altium_Footprint_Lib.PcbLib; Height: 8.58MM; Library Path: Y:\MIS_DATABASE\Library\ALTIUM_TOOL\SCHEMATICS_PARTS\MS_CONNECTOR_Library.schlib; Mfr_name: SAMTEC; Mfr_part_number: TSW-112-07-S-D; Mistral Part No: 150020040027-R; Package: THRU-HOLE; Part_type: CONNECTOR\HEADERS; Project: AM64x-GP_EVM BRD; RoHS: RoHS; Temperature: -55°C+125°C; Tolerance: NA; Voltage: NA; Wattage: NA; Weight: NA; Datasheet: Y:\MIS_DATABASE\DATASHEETS\CONNECTORS\SAM_TSW-SER.PDF
Q8 = MOSFET_IRLML6401TR: TRANSISTOR MOSFET P-CHANNEL SOT23-3; Chkd/date: SHREESHAIL/020206; Crtd /date: MAZHAR/040505; Custom_Duty: 15%; Customs_HS_Code: 85412900; Distributor_name: DIGIKEY; Distributor_part_number: IRLML6401PBFCT-ND; Height: 1.11MM; Mfr_name: IRF; Mfr_part_number: IRLML6401TRPBF; Mistral Part No: 130009031213-P; Package: SOT23-3; Part_type: TRANSISTOR\MOSFET; Project: G4_SVGA; RoHS: Pb-Free; Temperature: -55°C+150°C; Tolerance: NA; Voltage: NA; Wattage: NA; Weight: NA; Datasheet: Y:\MIS_DATABASE\DATASHEETS\DISCRETES\TRANSISTORS_FETS\IRLML6401.PDF
R302 = RESISTOR: RES 22E 1/16W 1% 0402; Chkd/date: SUHAS/290910; Crtd /date: MAZHAR/090909; Cust_part_number: 4700-80047E; Custom_Duty: 15%; Customs_HS_Code: 85332119; Distributor_name: DIGIKEY; Distributor_part_number: 311-22.0LRCT-ND; Footprint Path: Y:\MIS_DATABASE\Library\ALTIUM_TOOL\PCB_FOOTPRINTS\Altium_Footprint_Lib.PcbLib; Height: 0.40MM; Library Path: Y:\MIS_DATABASE\Library\ALTIUM_TOOL\SCHEMATICS_PARTS\MS_DISCRETE_Library.schlib; Mfr_name: YAGEO AMERICA; Mfr_part_number: RC0402FR-0722RL; Mistral Part No: 110009090004-R; Package: 0402; Part_type: RESISTORS\FIXED; Project: VMEFMCD; RoHS: RoHS; SIGNAL_MODEL: RESISTOR_RES0402_22E_22E; Temperature: -55°C+155°C; Tolerance: 1%; Voltage: NA; Wattage: 1/16W; Weight: 0.65mg; Datasheet: Y:\MIS_DATABASE\DATASHEETS\RESISTORS\RCXXXXL-SER_MAR18.PDF
R593 R594 R597 = RESISTOR: RES 620E 1/10W 1% 0402; Chkd/date: USMAN/120313; Crtd /date: CHAITHANYA/270912; Custom_Duty: 15%; Customs_HS_Code: 85332119; Distributor_name: DIGIKEY; Distributor_part_number: P620LCT-ND; Footprint Path: Y:\MIS_DATABASE\Library\ALTIUM_TOOL\PCB_FOOTPRINTS\Altium_Footprint_Lib.PcbLib; Height: 0.40MM; Library Path: Y:\MIS_DATABASE\Library\ALTIUM_TOOL\SCHEMATICS_PARTS\MS_DISCRETE_Library.schlib; Mfr_name: PANASONIC-ECG; Mfr_part_number: ERJ-2RKF6200X; Mistral Part No: 110012090013-R; Package: 0402; Part_type: RESISTORS\FIXED; Project: ITS-CONTROLER_CARD; RoHS: RoHS; Temperature: -55°C+155°C; Tolerance: 1%; Voltage: NA; Wattage: 1/10W; Weight: 0.8mg; Datasheet: Y:\MIS_DATABASE\DATASHEETS\RESISTORS\PAN-ERJSER_NOV17.PDF
SW6 = SW4_SKHUPLE010: SWITCH TACTILE SPST ST SMD; Chkd/date: MANIRAJA/051017; Crtd /date: MANIRAJA/051017; Custom_Duty: 24%; Customs_HS_Code: 85369090; Distributor_name: MOUSER; Distributor_part_number: 688-SKHMQLE010; Height: 3.10MM; Mfr_name: ALPS; Mistral Part No: 130017100007-R; Package: SMD; Part_type: ELECTRO-MECHANICAL\SWITCH; Project: TI_MAXIE_CPB; RoHS: RoHS; Temperature: -30°C+85°C; Tolerance: NA; Voltage: NA; Wattage: NA; Weight: NA; Datasheet: Y:\MIS_DATABASE\DATASHEETS\MISC\SWITCHES\SKHMQLE010.PDF
U35 = SN74LVC1G11DCKR_SC70-6: IC SINGLE 3-INPUT POSITIVE-AND GATE SC70-6; Chkd/date: SHREESHAIL/220506; Crtd /date: MAZHAR/150506; Custom_Duty: 15%; Customs_HS_Code: 85423100; Distributor_name: DIGIKEY; Distributor_part_number: 296-18066-1-ND; Height: 1.10MM; Mfr_name: TEXAS INSTRUMENTS; Mistral Part No: 141009030230-R; Part_type: ICS\DIGITAL\GATES; Project: VOCERA; RoHS: Sb/ Br FREE; Datasheet: Y:\MIS_DATABASE\DATASHEETS\ICS\DIGITAL\GATES\SN74LVC1G.PDF
Y1 = CRY4_ABM8G: CRY 25.000MHz 8pF SMD; Chkd/date: MANIRAJA/250620; Crtd /date: ALVY/250620; Custom_Duty: 24%; Customs_HS_Code: 85439000; Distributor_name: DIGIKEY; Distributor_part_number: 535-13736-1-ND; Footprint Path: Y:\MIS_DATABASE\Library\ALTIUM_TOOL\PCB_FOOTPRINTS\Altium_Footprint_Lib.PcbLib; Height: 0.60MM; Library Path: Y:\MIS_DATABASE\Library\ALTIUM_TOOL\SCHEMATICS_PARTS\MS_DISCRETE_Library.schlib; Mfr_name: ABRACON CORPORATION; Mfr_part_number: ABM10W-25.0000MHZ-8-K1Z-T3; Mistral Part No: 130020060044-R; Package: SMD; Part_type: CRYSTAL; Project: AM64x_SVB DUT BRD; RoHS: RoHS; Temperature: -40°C+125°C; Tolerance: NA; Voltage: NA; Wattage: NA; Weight: NA; Datasheet: Y:\MIS_DATABASE\DATASHEETS\MISC\CRY_OSC\ABM10W.PDF

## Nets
DGND: C5.1 C6.2 C10.2 C17.2 C21.1 C22.1 C30.1 C31.1 C32.2 C45.2 C50.2 C55.1 C72.1 C109.2 C117.1 C133.1 C134.1 C221.1 C444.1 C466.1 C485.1 C487.2 C488.2 C491.2 D9.1 J1.23 J4.3 J5.1 Q8.3(D) R140.1 R344.1 R348.1 R452.1 R606.2 SW6.3 SW6.4 SW6.5(GND) U1.7(GND) U6.1(A1) U6.7(GND) U10.2(GND) U11.7(GND) U14.1(A1) U14.2(A0) U14.7(GND) U16.2(A0) U16.7(GND) U28.7(GND) U35.2(GND) U91.25(GND) U91.33(EP) Y1.2(GND1) Y1.4(GND2) ; also on sheet 2 3 4 5 6 7 8 9 10 11 15 16 17 18 19 20 21 22 23 24 25 26 27 28 29 30 39 40
VCC1V2_DDR: C21.2 J8.1 R22.1 ; also on sheet 15
VCC1V8: C30.2 C221.2 C485.2 J13.1 R24.2 R233.2 R575.1 U10.3(VCCA) U35.5(VCC) ; also on sheet 11 15 18 21 24
VCC_3V3_SYS: C5.2 C6.1 C10.1 C17.1 C22.2 C32.1 C45.1 C50.1 C55.2 C109.1 C444.2 J1.1 J19.1 R6.2 R7.2 R47.2 R265.1 R270.1 R295.4 R303.1 R306.1 R309.1 R311.1 R465.2 R536.2 R574.1 U1.1(A1) U1.6(VS+) U6.2(A0) U6.6(VS+) U10.7(VCCB) U11.6(VS+) U14.6(VS+) U16.6(VS+) U28.6(VS+) U91.27(VCCP) U91.31(VCC) ; also on sheet 2 5 6 7 8 10 11 15 16 17 18 19 20 21 23 24 25 26 27 29 30 39 40
VCC_CORE: C72.2 J20.1 R92.3 ; also on sheet 15
VDD_0V85: C31.2 J11.1 R227.4 ; also on sheet 15
VDD_CORE: J20.2 R92.2 ; also on sheet 3 4 15 25
VDD_DDR4: J8.2 R22.4 ; also on sheet 3 4 16 22
VDDA1V8: C117.2 J22.1 R351.2 ; also on sheet 15
VDDA_1V8: J22.2 R351.3 ; also on sheet 3 4
VDDAR_CORE: J11.2 R227.1 ; also on sheet 4 15
ADDR_1: R452.2 U91.26(ADDR)
CAN_MUX_SEL: U91.2(P01) ; also on sheet 6
CDC_OE1/OE4: U91.18(P21) ; also on sheet 11
CONN_MCU_PORz: J1.24 R7.1 U35.3(B)
CONN_MCU_RESETz: J1.21 Q8.1(G) R6.1
CPSW_FET_SEL: U91.11(P12) ; also on sheet 2
DDR_VTT_EN: U10.5(A1) ; also on sheet 21
DDR_VTT_EN_3V3: U10.8(B1) ; also on sheet 16
Debounce_MCU_RESETz: C466.2 D9.2 Q8.2(S) R536.1 SW6.1 SW6.2 ; also on sheet 25
FSI_FET_SEL: U91.8(P07) ; also on sheet 19
GPIO_CPSW1_RST: U91.3(P02) ; also on sheet 2
GPIO_eMMC_RSTn: U91.1(P00) ; also on sheet 24
GPIO_OLED_RESETn: U91.15(P16) ; also on sheet 6
GPIO_PCIe_RST_OUT: U91.6(P05) ; also on sheet 5
GPIO_RGMII1_RST: U91.4(P03) ; also on sheet 40
GPIO_RGMII2_RST: U91.5(P04) ; also on sheet 39
INA_ALERT: J4.4 R1.2 R28.2 R43.2 R47.1 R48.2 R122.2 R244.2
IO_EXP_INTn_SDIO: R465.1 U91.32(~{INT}) ; also on sheet 24
MCAN0_STB_3V3: U91.9(P10) ; also on sheet 6
MCAN1_STB_3V3: U91.10(P11) ; also on sheet 6
MCU_GPIO0_6: J1.8 U23.B7(MCU_SPI1_CS1) ; also on sheet 25
MCU_GPIO0_7: J1.9 U23.D7(MCU_SPI1_CLK)
MCU_GPIO0_8: J1.5 U23.C7(MCU_SPI1_D0)
MCU_GPIO0_9: J1.12 U23.C8(MCU_SPI1_D1)
MCU_I2C0_SCL: J1.20 R311.2 R593.1
MCU_I2C0_SCL_RC: C487.1 R593.2 U23.E9(MCU_I2C0_SCL)
MCU_I2C0_SDA: J1.17 R309.2 R594.1
MCU_I2C0_SDA_RC: C488.1 R594.2 U23.A10(MCU_I2C0_SDA)
MCU_I2C1_SCL: J1.18 R306.2 U23.A11(MCU_I2C1_SCL)
MCU_I2C1_SDA: J1.14 R303.2 U23.B10(MCU_I2C1_SDA)
MCU_OSC0_XI: R137.2 R138.2 U23.C21(MCU_OSC0_XI)
MCU_OSC0_XO: R139.2 R140.2 U23.B20(MCU_OSC0_XO)
MCU_PORz: R575.2 R606.1 TP33.1(TP) U23.B21(MCU_PORZ) U35.4(Y) ; also on sheet 18
MCU_RESETSTATz: J1.19 TP1.1(TP) U23.B13(MCU_RESETSTATZ) ; also on sheet 18
MCU_RESETz: TP46.1(TP) U23.B12(MCU_RESETZ) ; also on sheet 18 25
MCU_SAFETY_ERRORz_1V8: TP72.1(TP) U10.4(A2) U23.A20(MCU_SAFETY_ERRORN)
MCU_SAFETY_ERRORz_3V3: J1.22 U10.1(B2)
MCU_SPI0_CLK: J1.16 R302.1
MCU_SPI0_CLK_R: R302.2 U23.E6(MCU_SPI0_CLK)
MCU_SPI0_CS0: J1.6 U23.D6(MCU_SPI0_CS0)
MCU_SPI0_CS1: J1.3 U23.C6(MCU_SPI0_CS1)
MCU_SPI0_D0: J1.4 U23.E7(MCU_SPI0_D0)
MCU_SPI0_D1: J1.2 U23.B6(MCU_SPI0_D1)
MCU_UART0_CTS_3V3: U23.D8(MCU_UART0_CTSN) ; also on sheet 23
MCU_UART0_RTS_3V3: U23.E8(MCU_UART0_RTSN) ; also on sheet 23
MCU_UART0_RX_3V3: U23.A9(MCU_UART0_RXD) ; also on sheet 23
MCU_UART0_TX_3V3: U23.A8(MCU_UART0_TXD) ; also on sheet 23
MCU_UART1_CTS_3V3: J1.10 U23.B8(MCU_UART1_CTSN)
MCU_UART1_RTS_3V3: J1.13 U23.B9(MCU_UART1_RTSN)
MCU_UART1_RX_3V3: J1.11 U23.C9(MCU_UART1_RXD)
MCU_UART1_TX_3V3: J1.15 U23.D9(MCU_UART1_TXD)
MMC1_SD_EN: U91.7(P06) ; also on sheet 24
PCIe_MCU_PORz: U35.6(C) ; also on sheet 5
PORz: R574.2 U35.1(A) ; also on sheet 25
PORz_OUT: R348.2 TP82.1(TP) U23.E17(PORZ_OUT) ; also on sheet 2 24 29 39 40
PRG1_RGMII2_FET_SEL: U91.13(P14) ; also on sheet 39
PRG1_RGMII_INTn: R597.1 ; also on sheet 2 39 40
PRG1_RGMII_INTn_RC: C491.1 R597.2 U23.C19(EXTINTN)
RESETSTATz: R344.2 TP68.1(TP) U23.F16(RESETSTATZ) U91.28(~{RESET}) ; also on sheet 5 11 21 24 29
SoC_CLKIN: R137.1 ; also on sheet 11
SOC_DVDD1V8: J13.2 R233.3 ; also on sheet 3 4
SoC_DVDD3V3: J19.2 R295.1 ; also on sheet 3 4
SoC_I2C0_SCL: J5.3 ; also on sheet 6 10 18
SoC_I2C0_SDA: J5.2 ; also on sheet 6 10 18
SoC_I2C1_SCL: R13.1 R265.2 U1.5(SCL) U6.5(SCL) U11.2(A0) U11.5(SCL) U14.5(SCL) U16.1(A1) U16.5(SCL) U28.1(A1) U28.5(SCL) U91.29(SCL) ; also on sheet 5 6 7 10 11 30
SoC_I2C1_SDA: R12.1 R270.2 U1.2(A0) U1.4(SDA) U6.4(SDA) U11.1(A1) U11.4(SDA) U14.4(SDA) U16.4(SDA) U28.2(A0) U28.4(SDA) U91.30(SDA) ; also on sheet 5 6 7 10 11 30
SoC_WARM_RESETZ: TP70.1(TP) U23.E18(RESET_REQZ) ; also on sheet 25
TEST_GPIO2: U91.14(P15) ; also on sheet 30
TEST_LED1: U91.17(P20) ; also on sheet 21
TEST_LED2: J1.7 U23.A7(MCU_SPI1_CS0) ; also on sheet 21
VPP_LDO_EN: U91.16(P17) ; also on sheet 15
N15854407: R43.1 U14.3(ALERT)
N15854417: C47.2 R73.1 U14.8(VBUS) U14.9(VIN-)
N15854427: C47.1 R74.1 U14.10(VIN+)
N15854463: R28.1 U6.3(ALERT)
N15854467: C204.2 R216.1 U6.8(VBUS) U6.9(VIN-)
N15854483: C204.1 R215.1 U6.10(VIN+)
N15854545: R244.1 U11.3(ALERT)
N15854547: R122.1 U28.3(ALERT)
N15854553: C214.2 R229.1 U11.8(VBUS) U11.9(VIN-)
N15854557: C393.2 R350.1 U28.8(VBUS) U28.9(VIN-)
N15854581: C393.1 R352.1 U28.10(VIN+)
N15854603: C214.1 R228.1 U11.10(VIN+)
N15854737: R1.1 U1.3(ALERT)
N15854741: C203.2 R11.1 U1.8(VBUS) U1.9(VIN-)
N15854757: C203.1 R10.1 U1.10(VIN+)
N15854857: J4.2 R12.2
N15854859: J4.1 R13.2
N17682848: R74.2 R92.4
N17682861: R73.2 R92.1
N17683733: R215.2 R227.3
N17683748: R216.2 R227.2
N17685678: R228.2 R233.1
N17685693: R229.2 R233.4
N17685736: R351.1 R352.2
N17685749: R350.2 R351.4
N17686321: R10.2 R22.2
N17686333: R11.2 R22.3
N24972917: R280.2 R295.3
N24972919: R281.2 R295.2
N24972921: C269.2 R281.1 U16.8(VBUS) U16.9(VIN-)
N24972925: C269.1 R280.1 U16.10(VIN+)
N24973001: R48.1 U16.3(ALERT)
N26648730: TP90.1(TP) U91.19(P22)
N26648748: TP88.1(TP) U91.20(P23)
N26648766: TP87.1(TP) U91.21(P24)
N26648784: TP86.1(TP) U91.22(P25)
N26648802: TP89.1(TP) U91.23(P26)
N26648820: TP91.1(TP) U91.24(P27)
N27838027: R24.1 U10.6(OE)
N27977097: C133.2 R138.1 Y1.1
N27977103: C134.2 R139.1 Y1.3
N28789368: TP101.1(TP) U91.12(P13)

Not connected (* = marked no-connect by the designer): J4 5*

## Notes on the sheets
sheet 12
- MCU_GENERAL
- 1V8
- 1V8
- SAFETY CONNECTOR
- LPF Designed for 25MHz Cutoff
  Have to change resistor and capacitor values accordingly
- pull-down resistor on PORz_OUT is provided to keep the signal
  low until the processor is released from reset during the
  power-up seqence
- Off Page Connections
- MCU WARM RESET
- To HSE Connector
- To level translator
- From Level Translator
- To Boot Mode Section
- From ICSSG Phy1&2
- To User LED
- From Push button
  Switch
sheet 13
- IO EXPANDER
- I2C ADDRESS: 0x22
- Off Page Connections
- I2C TEST HEADER
- 3V3 IO level
- SCL
- GND
- SDA
- From Safety Connector
- From SoC OSPI Section
- To Processor
- To SoC MMC
- To VTT Reg
- LEVEL TRANSLATOR
sheet 14
- CURRENT MONITORING  DEVICES
- VDD_CORE
- SoC_DVDD1V8
- I2C ADDRESS: 0x40
- I2C ADDRESS: 0x4B
- VDDAR_CORE
- VDDA_1V8
- I2C ADDRESS: 0x41
- I2C ADDRESS: 0x4E
- SoC_DVDD3V3
- VDD_DDR4
- INA I2C SLAVE ADDRESS
- I2C ADDRESS: 0x4C
- SLAVE
  ADDRESS
  (IN HEX)
- I2C ADDRESS: 0x46
- POWER SOURCE
- SUPPLY NET
- VCC_CORE
- VDD_CORE
- 40
- VDD_0V85
- VDDAR_CORE
- 41
- VCC_3V3_SYS
- SoC_DVDD3V3
- 4C
- VCC1V8
- SoC_DVDD1V8
- 4B
- VDDA1V8
- VDDA_1V8
- 4E
- VCC1V2_DDR
- VDD_DDR4
- 46
